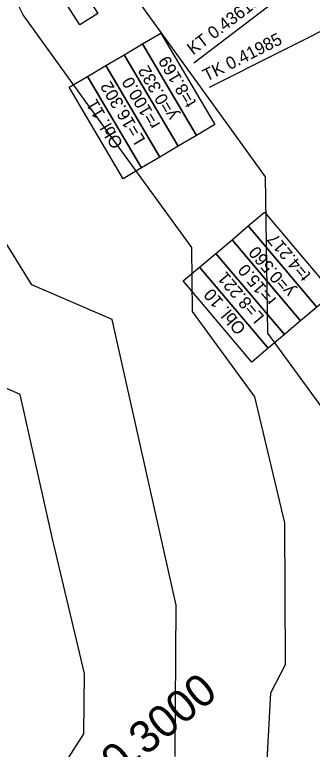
# Model space of a CAD drawing. Extents: x -549394 to -546608, y -1037055 to -1033629.
# Drawn here: x -548001.4 to -547917.4, y -1034785.5 to -1034578.2 of the extents above; entities that cross this region are included whole.
import ezdxf

# ---------------------------------------------------------------- set-up
doc = ezdxf.new("R2010")
doc.units = 0
for name, color, linetype in [('hlavni_vrst', 7, 'Continuous'), ('norm_vrst', 7, 'Continuous'), ('x_navrh_C21', 7, 'Continuous'), ('x_popis_oblouky_C21', 7, 'Continuous'), ('x_popis_pricne_rezy_C21', 7, 'Continuous')]:
    doc.layers.add(name, color=color, linetype=linetype)

msp = doc.modelspace()

# ---------------------------------------------------------------- linework, layer by layer
at = {"layer": 'hlavni_vrst'}
for p, q in [((-547998.99, -1034578.18), (-548017.39, -1034540.43)), ((-547982.19, -1034601.45), (-547998.99, -1034578.18)), ((-547951.4, -1034643.89), (-547982.19, -1034601.45)), ((-547951.14, -1034661.91), (-547951.4, -1034643.89)), ((-547933.58, -1034685.98), (-547951.14, -1034661.91)), ((-547925.09, -1034721.59), (-547933.58, -1034685.98)), ((-547924.9, -1034761.54), (-547925.09, -1034721.59)), ((-547929.09, -1034769.59), (-547924.9, -1034761.54)), ((-547930.28, -1034793.03), (-547929.09, -1034769.59))]:
    msp.add_line(p, q, dxfattribs=at)
at = {"layer": 'norm_vrst'}
for p, q in [((-547939.34, -1034611.82), (-547977.13, -1034559.46)), ((-547996.51, -1034654.45), (-548028.57, -1034603.4)), ((-547930.54, -1034623.95), (-547939.34, -1034611.82)), ((-547929.91, -1034668.08), (-547930.54, -1034623.95)), ((-547999.8, -1034685.36), (-548072.27, -1034654.17)), ((-547973.84, -1034664.21), (-547996.51, -1034654.45)), ((-547956.64, -1034741.01), (-547973.84, -1034664.21)), ((-547904.3, -1034703.2), (-547929.91, -1034668.08)), ((-547990.67, -1034726.1), (-547999.8, -1034685.36)), ((-547981.7, -1034764.08), (-547990.67, -1034726.1)), ((-547955.75, -1034744.77), (-547956.64, -1034741.01)), ((-547956.05, -1034787.56), (-547955.75, -1034744.77)), ((-547981.82, -1034781.1), (-547981.7, -1034764.08)), ((-547986.68, -1034788.68), (-547981.82, -1034781.1))]:
    msp.add_line(p, q, dxfattribs=at)
at = {"layer": 'x_navrh_C21'}
for radius, start, end in [(97.57, 25.4144, 36.9117), (97.82, 25.4026, 36.9086)]:
    msp.add_arc((-547995.81, -1034625.26), radius, start, end, dxfattribs=at)
at = {"layer": 'x_popis_oblouky_C21'}
for points in [[(-547982.94, -1034581.04), (-547999.14, -1034555.8), (-547994.09, -1034552.55), (-547977.89, -1034577.8)], [(-547950.06, -1034612.26), (-547965.32, -1034586.43), (-547960.15, -1034583.38), (-547944.89, -1034609.2)], [(-547955.22, -1034615.31), (-547970.48, -1034589.48), (-547965.32, -1034586.43), (-547950.06, -1034612.26)], [(-547960.39, -1034618.36), (-547975.65, -1034592.53), (-547970.48, -1034589.48), (-547955.22, -1034615.31)], [(-547965.56, -1034621.41), (-547980.82, -1034595.58), (-547975.65, -1034592.53), (-547960.39, -1034618.36)], [(-547970.72, -1034624.47), (-547985.98, -1034598.64), (-547980.82, -1034595.58), (-547965.56, -1034621.41)], [(-547916.07, -1034660.71), (-547935.44, -1034637.79), (-547930.85, -1034633.92), (-547911.49, -1034656.84)], [(-547920.66, -1034664.58), (-547940.02, -1034641.67), (-547935.44, -1034637.79), (-547916.07, -1034660.71)], [(-547925.24, -1034668.45), (-547944.6, -1034645.54), (-547940.02, -1034641.67), (-547920.66, -1034664.58)], [(-547929.82, -1034672.33), (-547949.19, -1034649.41), (-547944.6, -1034645.54), (-547925.24, -1034668.45)], [(-547934.41, -1034676.2), (-547953.77, -1034653.28), (-547949.19, -1034649.41), (-547929.82, -1034672.33)]]:
    msp.add_lwpolyline(points, close=True, dxfattribs=at)
for points in [[(-547915.85, -1034565.21), (-547950.8, -1034591.86)], [(-547907.16, -1034578.99), (-547946.45, -1034598.7)]]:
    msp.add_lwpolyline(points, dxfattribs=at)

# ---------------------------------------------------------------- texts
for s, rotation, p in [('KT 0.43615', 37.3171, (-547951.02, -1034589.69)), ('TK 0.41985', 26.642, (-547947.19, -1034597.1)), ('t=8.169', 120.5982, (-547949.98, -1034602.97)), ('y=0.332', 120.5982, (-547955.21, -1034606.6)), ('r=100.0', 120.5982, (-547960.17, -1034609.13)), ('L=16.302', 120.5982, (-547964.36, -1034613.5)), ('Obl. 11', 120.5982, (-547970.64, -1034614.66)), ('t=4.217', 130.2184, (-547917.55, -1034651.54)), ('y=0.560', 130.2184, (-547922.1, -1034655.99)), ('r=15.0', 130.2184, (-547927.32, -1034658.42)), ('L=8.221', 130.2184, (-547930.72, -1034663.43)), ('Obl. 10', 130.2184, (-547935.87, -1034666.64))]:
    msp.add_text(s, height=3.5, rotation=rotation, dxfattribs=at).set_placement(p)
at = {"layer": 'x_popis_pricne_rezy_C21'}
msp.add_text('PŘ 4 km 0.3000', height=9.0627, rotation=39.4445, dxfattribs=at).set_placement((-548010.7, -1034825.52))

doc.saveas('drawing.dxf')
